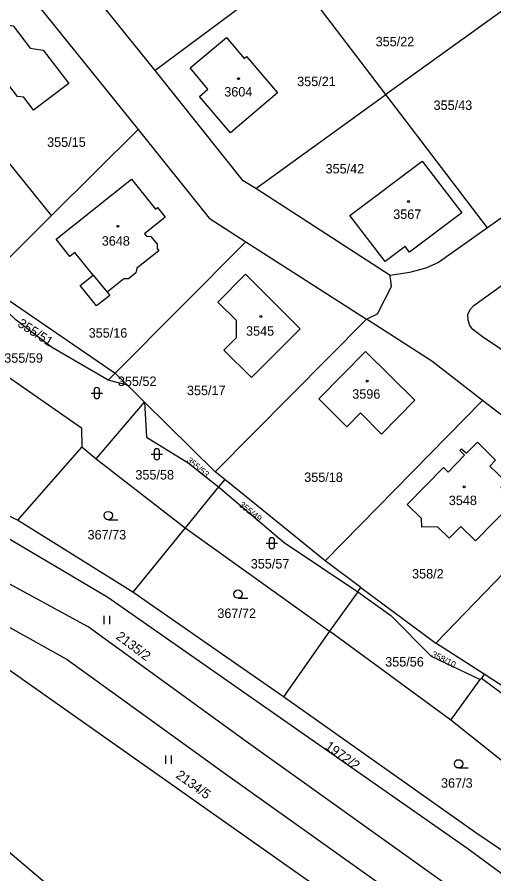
# Model space of a CAD drawing. Extents: x -679220 to -673243, y -1075091 to -1066557.
# Drawn here: x -675965.1 to -675879.3, y -1072921 to -1072766.7 of the extents above; entities that cross this region are included whole.
import ezdxf

# ---------------------------------------------------------------- set-up
doc = ezdxf.new("R2010")
doc.units = 0
for name, color, linetype in [('Hranice parcel', 7, 'Continuous'), ('Parcelní čísla', 7, 'Continuous'), ('Vnitřní kresba', 7, 'Continuous'), ('Značky budov', 7, 'Continuous'), ('Značky kultur', 7, 'Continuous')]:
    doc.layers.add(name, color=color, linetype=linetype)

msp = doc.modelspace()

# ---------------------------------------------------------------- linework, layer by layer
at = {"layer": 'Hranice parcel'}
for p, q in [((-675915.89, -1072758.12), (-675940.27, -1072776.25)), ((-675898.76, -1072780.62), (-675915.89, -1072758.12)), ((-675873.94, -1072762.75), (-675898.76, -1072780.62)), ((-675958.94, -1072802.41), (-675981.91, -1072774.03)), ((-675922.19, -1072797.5), (-675898.76, -1072780.62)), ((-675880.49, -1072804.63), (-675898.76, -1072780.62)), ((-675958.94, -1072802.41), (-675943.33, -1072786.91)), ((-675897.97, -1072813.17), (-675922.19, -1072797.5)), ((-675971.17, -1072814.56), (-675958.94, -1072802.41)), ((-675923.95, -1072807.12), (-675947.48, -1072830.77)), ((-675923.95, -1072807.12), (-675902.23, -1072821.05)), ((-675971.17, -1072814.56), (-675947.48, -1072830.77)), ((-675929.5, -1072848.56), (-675902.23, -1072821.05)), ((-675948.75, -1072832.04), (-675947.48, -1072830.77)), ((-675947.48, -1072830.77), (-675945.25, -1072832.97)), ((-675945.25, -1072832.97), (-675948.75, -1072832.04)), ((-675942.19, -1072836.01), (-675945.25, -1072832.97)), ((-675950.93, -1072846.24), (-675942.19, -1072836.01)), ((-675929.5, -1072848.56), (-675942.19, -1072836.01)), ((-675881.36, -1072835.7), (-675909.68, -1072864.61)), ((-675862.01, -1072850.62), (-675881.36, -1072835.7)), ((-675953.49, -1072844.05), (-675965.09, -1072857.25)), ((-675953.49, -1072844.05), (-675950.93, -1072846.24)), ((-675950.93, -1072846.24), (-675934.88, -1072858.66)), ((-675927.77, -1072849.96), (-675929.5, -1072848.56)), ((-675927.77, -1072849.96), (-675928.86, -1072851.25)), ((-675909.68, -1072864.61), (-675927.77, -1072849.96)), ((-675928.86, -1072851.25), (-675934.88, -1072858.66)), ((-675889.77, -1072879.39), (-675862.01, -1072850.62)), ((-675944.3, -1072870.24), (-675965.09, -1072857.25)), ((-675934.88, -1072858.66), (-675944.3, -1072870.24)), ((-675934.88, -1072858.66), (-675908.91, -1072877.27)), ((-675903.24, -1072869.39), (-675909.68, -1072864.61)), ((-675903.78, -1072870.17), (-675908.91, -1072877.27)), ((-675903.78, -1072870.17), (-675903.24, -1072869.39)), ((-675903.24, -1072869.39), (-675889.77, -1072879.39)), ((-675908.91, -1072877.27), (-675917.21, -1072889.07)), ((-675887.07, -1072893.31), (-675908.91, -1072877.27)), ((-675881.06, -1072885.03), (-675889.77, -1072879.39)), ((-675881.77, -1072885.97), (-675881.52, -1072885.71)), ((-675881.06, -1072885.03), (-675881.52, -1072885.71)), ((-675867.95, -1072893.53), (-675881.06, -1072885.03)), ((-675887.07, -1072893.31), (-675881.77, -1072885.97))]:
    msp.add_line(p, q, dxfattribs=at)
for points in [[(-675940.27, -1072776.25), (-675956.15, -1072756.56), (-675956.3, -1072756.05), (-675956.31, -1072755.06), (-675955.81, -1072754.19), (-675932.27, -1072736.37)], [(-675981.91, -1072774.03), (-675964.38, -1072760.75), (-675943.33, -1072786.91)], [(-675960.42, -1072772.59), (-675955.85, -1072778.63), (-675962.16, -1072783.41), (-675963.91, -1072781.11), (-675965.09, -1072780.97), (-675966.61, -1072778.93), (-675969.71, -1072778.49), (-675974.04, -1072781.77), (-675978.77, -1072775.44), (-675968.7, -1072767.81), (-675965.87, -1072768.22), (-675962.79, -1072772.26), (-675960.42, -1072772.59)], [(-675870.24, -1072767.69), (-675856.99, -1072785.25), (-675856.81, -1072786.25), (-675857.06, -1072787.21), (-675857.92, -1072788.44), (-675859.03, -1072789.43), (-675880.49, -1072804.63)], [(-675932.32, -1072780.95), (-675930.8, -1072779.63), (-675933.97, -1072775.81), (-675927.47, -1072770.31), (-675924.24, -1072774.1), (-675923.84, -1072773.75), (-675918.24, -1072780.32), (-675926.71, -1072787.53), (-675932.32, -1072780.95)], [(-675922.19, -1072797.5), (-675924.44, -1072796.13), (-675940.27, -1072776.25)], [(-675943.33, -1072786.91), (-675930.56, -1072802.88), (-675923.95, -1072807.12)], [(-675892.23, -1072792.58), (-675885.11, -1072801.91), (-675894.48, -1072809), (-675895.31, -1072807.95), (-675898.88, -1072810.65), (-675905.22, -1072802.42), (-675892.23, -1072792.58)], [(-675945.1, -1072813.79), (-675945.92, -1072813.78), (-675948.93, -1072816.18), (-675948.45, -1072816.82), (-675950.87, -1072818.69), (-675953.76, -1072814.98), (-675951.46, -1072813.13), (-675954.73, -1072809.08), (-675955.66, -1072809.77), (-675958.13, -1072806.63), (-675944.54, -1072795.83), (-675940.24, -1072801.26), (-675939.85, -1072800.95), (-675938.48, -1072802.68), (-675942.22, -1072805.67), (-675941.83, -1072806.12), (-675941.05, -1072806.18), (-675939.92, -1072807.57), (-675939.94, -1072808.36), (-675939.62, -1072808.75), (-675943.56, -1072811.9), (-675943.74, -1072812.72), (-675945.1, -1072813.79)], [(-675852.87, -1072947.94), (-675923.92, -1072897.14), (-675952.34, -1072876.46), (-675990.88, -1072855.55), (-676033.92, -1072836.1), (-676058.2, -1072815.36), (-676065.61, -1072804.81)], [(-676065.61, -1072804.81), (-676057.1, -1072814.26), (-676037, -1072828.59), (-676029.23, -1072831.66), (-676001.87, -1072843.09), (-675975.54, -1072855.33), (-675948.8, -1072871.14), (-675884.19, -1072916.3), (-675865.43, -1072930.06), (-675852.87, -1072947.94)], [(-675880.49, -1072804.63), (-675889.31, -1072810.87), (-675891.58, -1072811.9), (-675894.49, -1072812.68), (-675897.97, -1072813.17)], [(-675854.85, -1072844.46), (-675878.51, -1072826.16), (-675881.13, -1072824.41), (-675883.1, -1072822.94), (-675883.62, -1072822.18), (-675883.97, -1072821.24), (-675883.98, -1072820.24), (-675883.57, -1072819.34), (-675882.9, -1072818.59), (-675869.77, -1072809.11)], [(-675914.19, -1072822.78), (-675922.92, -1072831.58), (-675927.91, -1072826.62), (-675925.65, -1072824.36), (-675925.67, -1072821.32), (-675928.99, -1072817.99), (-675924.04, -1072812.98), (-675914.19, -1072822.78)], [(-675902.23, -1072821.05), (-675900.25, -1072820.12), (-675897.76, -1072815.21), (-675897.97, -1072813.17)], [(-675948.75, -1072832.04), (-675958.95, -1072826.11), (-675965.33, -1072821.26), (-675971.74, -1072815.13)], [(-675982.29, -1072820.62), (-675953.52, -1072840.64), (-675953.49, -1072844.05)], [(-675881.36, -1072835.7), (-675890.5, -1072828.63), (-675902.23, -1072821.05)], [(-675899.52, -1072841.75), (-675903.34, -1072837.93), (-675905.81, -1072840.45), (-675910.85, -1072835.44), (-675902.43, -1072826.88), (-675893.57, -1072835.67), (-675899.52, -1072841.75)], [(-675942.19, -1072836.01), (-675941.86, -1072842.33), (-675934.36, -1072846.91), (-675928.86, -1072851.25)], [(-675965.09, -1072857.25), (-675988.11, -1072845.73), (-675997.35, -1072840.95)], [(-675885.43, -1072844.73), (-675885.12, -1072844.41), (-675884.25, -1072845.21), (-675882.28, -1072843.2), (-675879.01, -1072846.47), (-675880.02, -1072847.51), (-675877.09, -1072850.37), (-675878.08, -1072851.37), (-675875.58, -1072853.85), (-675882.6, -1072860.97), (-675885.26, -1072858.43), (-675887.37, -1072860.5), (-675889.47, -1072858.47), (-675892.28, -1072858.55), (-675892.37, -1072856.99), (-675894.93, -1072854.45), (-675888.41, -1072847.78), (-675887.56, -1072848.62), (-675884.58, -1072845.56), (-675885.43, -1072844.73)], [(-675793.98, -1073004.25), (-675847.84, -1072968.03), (-675970.96, -1072881.23), (-675995.4, -1072866.92), (-676015.48, -1072856.38), (-676040.93, -1072851.33)], [(-675748.91, -1073099.96), (-675833.86, -1073028.13), (-675906.4, -1072968.21), (-675995.92, -1072892.2), (-676032.53, -1072861.26), (-676040.93, -1072851.33)], [(-675928.86, -1072851.25), (-675917.08, -1072861.27), (-675903.78, -1072870.17)], [(-676002.17, -1072857.32), (-675993.29, -1072861.62), (-675956.13, -1072882.34), (-675927.65, -1072902.94), (-675848.02, -1072959.69), (-675843.66, -1072961.37)], [(-675917.21, -1072889.07), (-675927.36, -1072881.99), (-675944.3, -1072870.24)], [(-675903.78, -1072870.17), (-675897.86, -1072874.45), (-675890.61, -1072881.74), (-675881.77, -1072885.97)], [(-675881.52, -1072885.71), (-675871.37, -1072893.31), (-675866.22, -1072895.2)], [(-675857.72, -1072930.41), (-675882.54, -1072913.59), (-675917.21, -1072889.07)], [(-675836.14, -1072925.5), (-675844.57, -1072916.55), (-675862.06, -1072906.91), (-675867.49, -1072905.51), (-675872.58, -1072904.79), (-675887.07, -1072893.31)]]:
    msp.add_lwpolyline(points, dxfattribs=at)
at = {"layer": 'Vnitřní kresba'}
msp.add_line((-675951.46, -1072813.13), (-675948.93, -1072816.18), dxfattribs=at)
at = {"layer": 'Značky budov'}
for centre in [(-675925.29, -1072777.75), (-675894.71, -1072799.85), (-675946.99, -1072804.34), (-675921.27, -1072820.58), (-675902.1, -1072832.23), (-675884.65, -1072851.25)]:
    msp.add_circle(centre, 0.175, dxfattribs=at)
at = {"layer": 'Značky kultur'}
for p, q in [((-675951.79, -1072834.38), (-675949.79, -1072834.38)), ((-675951.29, -1072833.88), (-675951.29, -1072834.88)), ((-675950.29, -1072834.88), (-675950.29, -1072833.88)), ((-675940.99, -1072845.39), (-675938.99, -1072845.39)), ((-675940.49, -1072844.89), (-675940.49, -1072845.89)), ((-675939.49, -1072845.89), (-675939.49, -1072844.89)), ((-675948.73, -1072857.19), (-675946.98, -1072857.19)), ((-675919.78, -1072860.92), (-675919.78, -1072861.92)), ((-675918.78, -1072861.92), (-675918.78, -1072860.92)), ((-675920.28, -1072861.42), (-675918.28, -1072861.42)), ((-675925.37, -1072871.33), (-675923.62, -1072871.33)), ((-675949.46, -1072875.99), (-675949.46, -1072874.49)), ((-675948.46, -1072875.99), (-675948.46, -1072874.49)), ((-675938.37, -1072901.17), (-675938.37, -1072899.67)), ((-675937.37, -1072901.17), (-675937.37, -1072899.67)), ((-675885.67, -1072901.9), (-675883.92, -1072901.9))]:
    msp.add_line(p, q, dxfattribs=at)
for centre in [(-675948.73, -1072856.44), (-675925.37, -1072870.58), (-675885.67, -1072901.15)]:
    msp.add_circle(centre, 0.75, dxfattribs=at)
for centre, start, end in [((-675950.79, -1072833.88), 0, 180), ((-675950.79, -1072834.88), 180, 359.9879), ((-675939.99, -1072844.89), 0, 180), ((-675939.99, -1072845.89), 180, 359.9879), ((-675919.28, -1072860.92), 0, 180), ((-675919.28, -1072861.92), 180, 359.9879)]:
    msp.add_arc(centre, 0.5, start, end, dxfattribs=at)

# ---------------------------------------------------------------- texts
at = {"layer": 'Parcelní čísla'}
for s, p in [('355/22', (-675900.6, -1072771.92)), ('355/21', (-675914.73, -1072779.09)), ('3604', (-675927.85, -1072780.96)), ('355/43', (-675890.17, -1072783.38)), ('355/15', (-675959.74, -1072790.03)), ('355/42', (-675909.62, -1072794.82)), ('3567', (-675897.44, -1072803.01)), ('3648', (-675949.9, -1072807.82)), ('3545', (-675923.93, -1072824.04)), ('355/16', (-675952.26, -1072824.39)), ('355/59', (-675967.46, -1072828.91)), ('355/52', (-675947, -1072833.1)), ('355/17', (-675934.57, -1072834.75)), ('3596', (-675904.81, -1072835.39)), ('355/58', (-675943.85, -1072849.94)), ('355/18', (-675913.46, -1072850.38)), ('3548', (-675887.43, -1072854.55)), ('367/73', (-675952.46, -1072860.74)), ('355/57', (-675923.08, -1072865.97)), ('358/2', (-675894.04, -1072867.77)), ('367/72', (-675929.09, -1072874.88)), ('355/56', (-675898.88, -1072883.63)), ('367/3', (-675888.83, -1072905.45))]:
    msp.add_text(s, height=1.7, dxfattribs=at).set_placement(p)
for s, height, rotation, p in [('355/51', 1.7, 327, (-675965.19, -1072822.25)), ('355/53', 1.14, 320, (-675934.73, -1072846.67)), ('355/49', 1.14, 321, (-675925.28, -1072854.68)), ('2135/2', 1.7, 323, (-675947.47, -1072878.51)), ('358/10', 1.14, 333, (-675890.67, -1072881.79)), ('1972/2', 1.7, 324, (-675909.85, -1072898.3)), ('2134/5', 1.7, 324, (-675936.69, -1072903.52))]:
    msp.add_text(s, height=height, rotation=rotation, dxfattribs=at).set_placement(p)

doc.saveas('drawing.dxf')
